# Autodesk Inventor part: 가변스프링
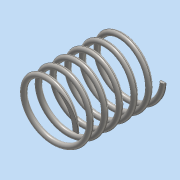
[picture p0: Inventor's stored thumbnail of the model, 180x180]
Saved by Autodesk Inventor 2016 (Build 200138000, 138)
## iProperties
Created: 2018-11
Part Number: 가변스프링
Material: 스테인레스 스틸
Document SubType Name: Modeling
Designer: user
Density: 8 g/cm^3
Appearance: 반연마
Mass: 84.1985 g
Surface Area: 106.475 cm^2
Volume: 10.5248 cm^3
Author: user
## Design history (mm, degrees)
sketch "스케치1"
  geometry: L1 (0, 0)-(22.5, 0); L2 (22.5, 0)-(22.5, 67.25); L3 (22.5, 67.25)-(0, 67.25); L4 (0, 67.25)-(0, 0); C1 r 2 at (22.5, 0)
  constraints: 8 end point, 2 parallel, 1 centre point, 1 coincident, 1 horizontal, 1 perpendicular
  dimensions: "d0" = 4 diameter of C1; "d1" = 45 diameter of L2 L4; "d2" = 67.25 distance of L3.end L1.start (derived)
feature "코일1" sketch "스케치1" pitch "d3" = 10; turns "d5" = 6; dims "d4" = 67.25 (= d2), "d6" = 0, angle "d7" = 90 deg, angle "d8" = 90 deg, "d9" = 0, "d10" = 0
sketch "스케치2"
  geometry: L1 (-36.387, 67.25)-(36.387, 67.25); L2 (36.387, 67.25)-(36.387, 0); L3 (36.387, 0)-(-36.387, 0); L4 (-36.387, 0)-(-36.387, 67.25); 2 further points
  constraints: 8 end point, 2 parallel, 1 coincident, 1 horizontal, 1 midpoint, 1 perpendicular
  dimensions: "d11" = 72.77407 distance of L1.start L1.end; "d12" = 67.25 distance of L3.end L1.start (= d2)
extrude "돌출1" sketch "스케치2" stored distance "d13" = 100; taper "d14" = 0 deg
node "솔리드1"
